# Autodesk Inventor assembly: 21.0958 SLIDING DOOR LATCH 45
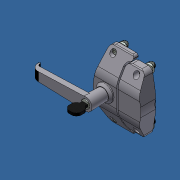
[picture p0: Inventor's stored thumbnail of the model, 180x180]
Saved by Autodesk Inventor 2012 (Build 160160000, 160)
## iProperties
Created: 2014-05
Part Number: 21.0958 SLIDING DOOR LATCH 45
Document SubType Name: Assembly
Designer: Admin
Author: Admin
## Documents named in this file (3)
- C:\Andys Backup Data\ANDY'S INVENTOR\INVENTOR LIBRARIES\PARTS LIBRARY\HANDLES LOCKS STOPS\21.0958 SLIDING DOOR LATCH 45.iam
- C:\Andys Backup Data\ANDY'S INVENTOR\INVENTOR LIBRARIES\PARTS LIBRARY\HANDLES LOCKS STOPS\SUBCOMPONENTS\21.0958 SLIDING DOOR LATCH HANDLE SIDE.ipt
- C:\Andys Backup Data\ANDY'S INVENTOR\INVENTOR LIBRARIES\PARTS LIBRARY\HANDLES LOCKS STOPS\SUBCOMPONENTS\21.0958 SLIDING DOOR LATCH CATCH SIDE.ipt
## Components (2 placed, 2 different names)
1. 21.0958 SLIDING DOOR LATCH HANDLE SIDE:1 — Flush:1, Mate:1, Flush:2
2. 21.0958 SLIDING DOOR LATCH CATCH SIDE:1 — Flush:1, Mate:1, Flush:2
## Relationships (3: Flush 2, Mate 1)
- Flush:1: 21.0958 SLIDING DOOR LATCH HANDLE SIDE:1 ↔ 21.0958 SLIDING DOOR LATCH CATCH SIDE:1
- Mate:1: 21.0958 SLIDING DOOR LATCH HANDLE SIDE:1 ↔ 21.0958 SLIDING DOOR LATCH CATCH SIDE:1
- Flush:2: 21.0958 SLIDING DOOR LATCH HANDLE SIDE:1 ↔ 21.0958 SLIDING DOOR LATCH CATCH SIDE:1
